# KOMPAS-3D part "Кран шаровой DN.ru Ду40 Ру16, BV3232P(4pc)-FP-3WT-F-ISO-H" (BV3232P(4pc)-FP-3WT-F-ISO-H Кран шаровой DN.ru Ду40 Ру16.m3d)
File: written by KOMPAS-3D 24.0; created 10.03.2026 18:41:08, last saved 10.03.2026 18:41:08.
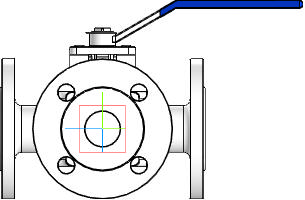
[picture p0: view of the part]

Document properties: Автор: R2D2; Полное имя файла: E:\Работа\Зайцев\BV3232P(4pc)-FP-3WT-F-ISO-H Кран шаровой DN.ru Ду15-100 Ру16\DN40\BV3232P(4pc)-FP-3WT-F-ISO-H Кран шаровой DN.ru Ду40 Ру16.m3d

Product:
- Part/product: Кран шаровой DN.ru Ду40 Ру16  | designation BV3232P(4pc)-FP-3WT-F-ISO-H
    Масса: 11.65
    Раздел спецификации: Прочие изделия
    Примечание: D160-36350

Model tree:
1. Операция без истории:1

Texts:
  BV3232P(4pc)-FP-3WT-F-ISO-H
